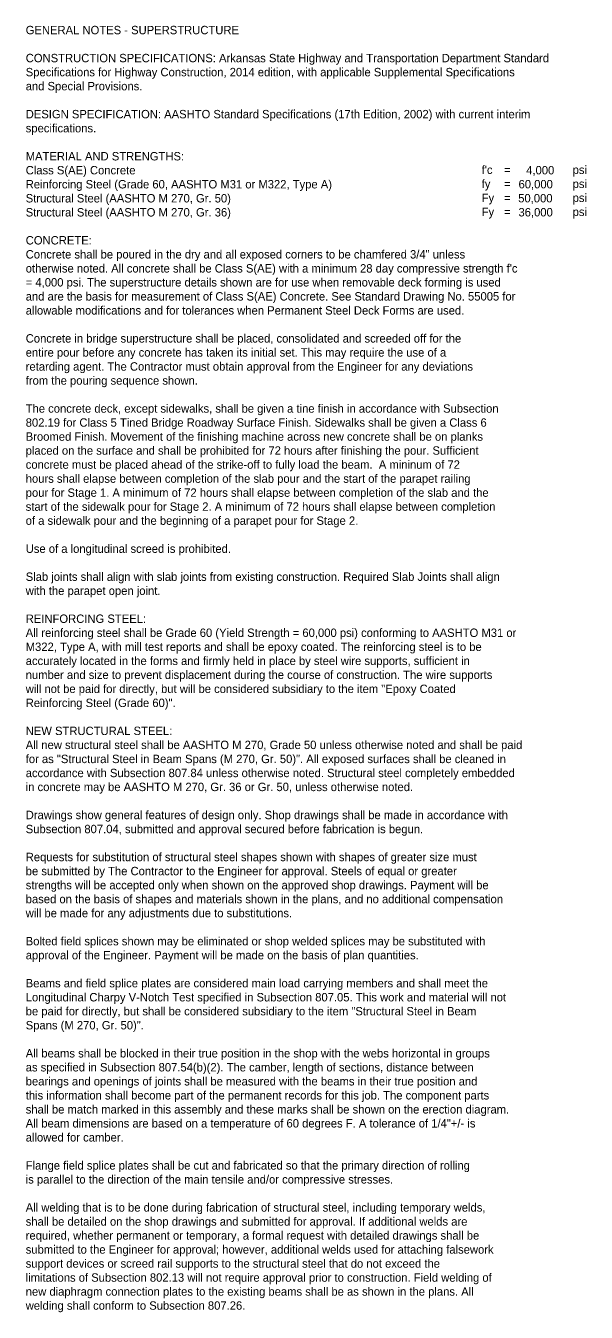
# Model space of a CAD drawing. Extents: x -30247.3 to -30217, y 5204.9 to 5224.7.
# Drawn here: x -30247.33 to -30238.98, y 5205.5 to 5224.66 of the extents above; entities that cross this region are included whole.
import ezdxf

# ---------------------------------------------------------------- set-up
doc = ezdxf.new("R2010")
doc.units = 0
doc.layers.add('B_Text', color=7, linetype='Continuous')

msp = doc.modelspace()

# ---------------------------------------------------------------- texts
at = {"layer": 'B_Text'}
for s, p in [('GENERAL NOTES - SUPERSTRUCTURE', (-30247.333, 5224.529)), ('CONSTRUCTION SPECIFICATIONS: Arkansas State Highway and Transportation Department Standard ', (-30247.333, 5224.112)), ('Specifications for Highway Construction, 2014 edition, with applicable Supplemental Specifications ', (-30247.333, 5223.903)), ('and Special Provisions.', (-30247.333, 5223.694)), ('DESIGN SPECIFICATION: AASHTO Standard Specifications (17th Edition, 2002) with current interim ', (-30247.333, 5223.277)), ('specifications.', (-30247.333, 5223.068)), ('MATERIAL AND STRENGTHS:', (-30247.333, 5222.65)), ('Class S(AE) Concrete', (-30247.333, 5222.442)), ("f'c", (-30240.542, 5222.448)), ('=', (-30240.21, 5222.448)), ('4,000', (-30239.879, 5222.442)), ('psi', (-30239.187, 5222.448)), ('Reinforcing Steel (Grade 60, AASHTO M31 or M322, Type A)', (-30247.333, 5222.233)), ('fy', (-30240.542, 5222.239)), ('=', (-30240.21, 5222.239)), ('60,000', (-30239.993, 5222.234)), ('psi', (-30239.187, 5222.239)), ('Structural Steel (AASHTO M 270, Gr. 50)', (-30247.333, 5222.024)), ('Fy', (-30240.542, 5222.031)), ('=', (-30240.21, 5222.031)), ('50,000', (-30239.998, 5222.025)), ('psi', (-30239.187, 5222.031)), ('Structural Steel (AASHTO M 270, Gr. 36)', (-30247.333, 5221.815)), ('Fy', (-30240.542, 5221.822)), ('=', (-30240.21, 5221.822)), ('36,000', (-30239.994, 5221.816)), ('psi', (-30239.187, 5221.822)), ('CONCRETE:', (-30247.333, 5221.398)), ('Concrete shall be poured in the dry and all exposed corners to be chamfered 3/4" unless ', (-30247.333, 5221.189)), ("otherwise noted. All concrete shall be Class S(AE) with a minimum 28 day compressive strength f'c ", (-30247.333, 5220.98)), ('= 4,000 psi. The superstructure details shown are for use when removable deck forming is used ', (-30247.333, 5220.772)), ('and are the basis for measurement of Class S(AE) Concrete. See Standard Drawing No. 55005 for ', (-30247.333, 5220.563)), ('allowable modifications and for tolerances when Permanent Steel Deck Forms are used.', (-30247.333, 5220.354)), ('Concrete in bridge superstructure shall be placed, consolidated and screeded off for the ', (-30247.333, 5219.937)), ('entire pour before any concrete has taken its initial set. This may require the use of a ', (-30247.333, 5219.728)), ('retarding agent. The Contractor must obtain approval from the Engineer for any deviations ', (-30247.333, 5219.519)), ('from the pouring sequence shown.', (-30247.333, 5219.31)), ('The concrete deck, except sidewalks, shall be given a tine finish in accordance with Subsection ', (-30247.333, 5218.893)), ('802.19 for Class 5 Tined Bridge Roadway Surface Finish. Sidewalks shall be given a Class 6 ', (-30247.333, 5218.684)), ('Broomed Finish. Movement of the finishing machine across new concrete shall be on planks ', (-30247.333, 5218.475)), ('placed on the surface and shall be prohibited for 72 hours after finishing the pour. Sufficient ', (-30247.333, 5218.267)), ('concrete must be placed ahead of the strike-off to fully load the beam.  A mininum of 72 ', (-30247.333, 5218.058)), ('hours shall elapse between completion of the slab pour and the start of the parapet railing ', (-30247.333, 5217.849)), ('pour for Stage 1. A minimum of 72 hours shall elapse between completion of the slab and the ', (-30247.333, 5217.64)), ('start of the sidewalk pour for Stage 2. A minimum of 72 hours shall elapse between completion ', (-30247.333, 5217.432)), ('of a sidewalk pour and the beginning of a parapet pour for Stage 2. ', (-30247.333, 5217.223)), ('Use of a longitudinal screed is prohibited.', (-30247.333, 5216.805)), ('Slab joints shall align with slab joints from existing construction. Required Slab Joints shall align ', (-30247.333, 5216.388)), ('with the parapet open joint.', (-30247.333, 5216.179)), ('REINFORCING STEEL:', (-30247.333, 5215.762)), ('All reinforcing steel shall be Grade 60 (Yield Strength = 60,000 psi) conforming to AASHTO M31 or ', (-30247.333, 5215.553)), ('M322, Type A, with mill test reports and shall be epoxy coated. The reinforcing steel is to be ', (-30247.333, 5215.344)), ('accurately located in the forms and firmly held in place by steel wire supports, sufficient in ', (-30247.333, 5215.135)), ('number and size to prevent displacement during the course of construction. The wire supports ', (-30247.333, 5214.927)), ('will not be paid for directly, but will be considered subsidiary to the item "Epoxy Coated ', (-30247.333, 5214.718)), ('Reinforcing Steel (Grade 60)".', (-30247.333, 5214.509)), ('NEW STRUCTURAL STEEL:', (-30247.333, 5214.092)), ('All new structural steel shall be AASHTO M 270, Grade 50 unless otherwise noted and shall be paid ', (-30247.333, 5213.883)), ('for as "Structural Steel in Beam Spans (M 270, Gr. 50)". All exposed surfaces shall be cleaned in ', (-30247.333, 5213.674)), ('accordance with Subsection 807.84 unless otherwise noted. Structural steel completely embedded ', (-30247.333, 5213.465)), ('in concrete may be AASHTO M 270, Gr. 36 or Gr. 50, unless otherwise noted.', (-30247.333, 5213.257)), ('Drawings show general features of design only. Shop drawings shall be made in accordance with ', (-30247.333, 5212.839)), ('Subsection 807.04, submitted and approval secured before fabrication is begun.', (-30247.333, 5212.63)), ('Requests for substitution of structural steel shapes shown with shapes of greater size must ', (-30247.333, 5212.213)), ('be submitted by The Contractor to the Engineer for approval. Steels of equal or greater ', (-30247.333, 5212.004)), ('strengths will be accepted only when shown on the approved shop drawings. Payment will be ', (-30247.333, 5211.795)), ('based on the basis of shapes and materials shown in the plans, and no additional compensation ', (-30247.333, 5211.587)), ('will be made for any adjustments due to substitutions.', (-30247.333, 5211.378)), ('Bolted field splices shown may be eliminated or shop welded splices may be substituted with ', (-30247.333, 5210.96)), ('approval of the Engineer. Payment will be made on the basis of plan quantities.', (-30247.333, 5210.752)), ('Beams and field splice plates are considered main load carrying members and shall meet the ', (-30247.333, 5210.334)), ('Longitudinal Charpy V-Notch Test specified in Subsection 807.05. This work and material will not ', (-30247.333, 5210.125)), ('be paid for directly, but shall be considered subsidiary to the item "Structural Steel in Beam ', (-30247.333, 5209.917)), ('Spans (M 270, Gr. 50)".', (-30247.333, 5209.708)), ('All beams shall be blocked in their true position in the shop with the webs horizontal in groups ', (-30247.333, 5209.29)), ('as specified in Subsection 807.54(b)(2). The camber, length of sections, distance between ', (-30247.333, 5209.082)), ('bearings and openings of joints shall be measured with the beams in their true position and ', (-30247.333, 5208.873)), ('this information shall become part of the permanent records for this job. The component parts ', (-30247.333, 5208.664)), ('shall be match marked in this assembly and these marks shall be shown on the erection diagram. ', (-30247.333, 5208.455)), ('All beam dimensions are based on a temperature of 60 degrees F. A tolerance of 1/4"+/- is ', (-30247.333, 5208.247)), ('allowed for camber.', (-30247.333, 5208.038)), ('Flange field splice plates shall be cut and fabricated so that the primary direction of rolling ', (-30247.333, 5207.62)), ('is parallel to the direction of the main tensile and/or compressive stresses.', (-30247.333, 5207.412)), ('All welding that is to be done during fabrication of structural steel, including temporary welds, ', (-30247.333, 5206.994)), ('shall be detailed on the shop drawings and submitted for approval. If additional welds are ', (-30247.333, 5206.785)), ('required, whether permanent or temporary, a formal request with detailed drawings shall be ', (-30247.333, 5206.577)), ('submitted to the Engineer for approval; however, additional welds used for attaching falsework ', (-30247.333, 5206.368)), ('support devices or screed rail supports to the structural steel that do not exceed the ', (-30247.333, 5206.159)), ('limitations of Subsection 802.13 will not require approval prior to construction. Field welding of ', (-30247.333, 5205.95)), ('new diaphragm connection plates to the existing beams shall be as shown in the plans. All ', (-30247.333, 5205.742)), ('welding shall conform to Subsection 807.26.', (-30247.333, 5205.533))]:
    msp.add_text(s, height=0.125, dxfattribs=at).set_placement(p)

doc.saveas('drawing.dxf')
